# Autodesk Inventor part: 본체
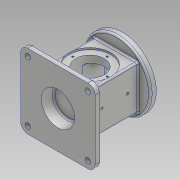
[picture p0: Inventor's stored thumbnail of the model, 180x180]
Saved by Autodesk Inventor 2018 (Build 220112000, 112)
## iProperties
Created: 2021-05
Part Number: 본체
Material: 알루미늄 6061
Document SubType Name: Modeling
Designer: home
Density: 2.7 g/cm^3
Appearance: 알루미늄 - 평지
Mass: 1251.58 g
Surface Area: 895.233 cm^2
Volume: 463.547 cm^3
Author: home
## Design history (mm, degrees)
sketch "스케치2"
  geometry: L1 (37, -37)-(-37, -37); L2 (-37, -37)-(-37, 37); L3 (-37, 37)-(37, 37); L4 (37, 37)-(37, -37); 1 further point
  constraints: 8 end point, 2 parallel, 1 horizontal, 1 perpendicular
  dimensions: "d4" = 74 distance between parallel lines of L2 L4; "d5" = 74 distance between parallel lines of L3 L1; "d6" = 37 distance from line of point (0, 0) L1; "d7" = 37 distance from line of point (0, 0) L4
extrude "돌출1" new body sketch "스케치2" distance "d8" = 88; taper "d9" = 0 deg
sketch "스케치3"
  geometry: L1 (74, 0)-(0, 0) reference; C1 r 24 at (37, 44); 2 further points
  constraints: 1 centre point, 1 midpoint, 1 vertical alignment
  dimensions: "d10" = 48 diameter of C1; "d11" = 44 distance from line of L1 C1.centre
extrude "돌출2" cut sketch "스케치3" distance "d12" = 88; taper "d13" = 0 deg
sketch "스케치4"
  geometry: C1 r 57.5 at (0, 0); 1 further point
  constraints: 1 centre point, 1 coincident
  dimensions: "d14" = 115 diameter of C1
extrude "돌출3" join sketch "스케치4" distance "d15" = 10; taper "d16" = 0 deg
sketch "스케치7"
  geometry: L1 (74, 0)-(0, 0) reference; L2 (74, 0)-(74, 88) reference; L3 (0, 88)-(74, 88) reference; L4 (0, 0)-(0, 88) reference; C1 r 24 at (37, 44) reference; C2 r 35 at (37, 44); 1 further point
  constraints: 1 centre point, 1 coincident
  dimensions: "d23" = 70 diameter of C2
extrude "돌출6" cut sketch "스케치7" distance "d24" = 3; taper "d25" = 0 deg
sketch "스케치8"
  geometry: L1 (37, -44)-(-37, -44) reference; C1 r 24 at (0, 0) reference; C2 r 35 at (0, 0) reference; 3 further points
  constraints: 1 midpoint, 1 vertical alignment
  dimensions: "d27" = 29 distance of point (0, 29) C1.centre
hole "구멍1" sketch "스케치8" at (0, 29) diameter "d28" = 3.242; stored, may be unused: countersink angle "d32" = 90 deg, drill point angle "d34" = 118 deg; dims "d29" = 8, "d30" = 4, "d31" = 2, "d33" = 10
sketch "스케치9"
  geometry: L1 (74, 0)-(0, 0) reference; 5 further points
  constraints: 2 midpoint, 2 vertical alignment
  dimensions: "d38" = 43 distance of point (37, 70) point (37, 27); "d39" = 27 distance of point (37, 0) point (37, 27)
hole "구멍2" sketch "스케치9" at (37, 70), (37, 27) diameter "d40" = 4.134; stored, may be unused: countersink angle "d44" = 90 deg, drill point angle "d46" = 118 deg; dims "d41" = 30, "d42" = 4, "d43" = 2, "d45" = 30
sketch "스케치10"
  geometry: L1 (-26, -26)-(26, -26); L2 (26, -26)-(26, 26); L3 (26, 26)-(-26, 26); L4 (-26, 26)-(-26, -26); 1 further point
  constraints: 8 end point, 2 parallel, 1 horizontal, 1 perpendicular
  dimensions: "d47" = 26 distance from line of point (0, 0) L1; "d48" = 52 distance between parallel lines of L3 L1; "d49" = 26 distance from line of point (0, 0) L4; "d50" = 52 distance between parallel lines of L2 L4
extrude "돌출7" cut sketch "스케치10" distance "d51" = 8; taper "d52" = 0 deg
sketch "스케치11"
  geometry: L1 (-22, -22)-(22, -22); L2 (22, -22)-(22, 22); L3 (22, 22)-(-22, 22); L4 (-22, 22)-(-22, -22); 1 further point
  constraints: 8 end point, 2 parallel, 1 horizontal, 1 perpendicular
  dimensions: "d53" = 22 distance from line of point (0, 0) L1; "d54" = 44 distance between parallel lines of L3 L1; "d55" = 22 distance from line of L4 point (0, 0); "d56" = 44 distance between parallel lines of L2 L4
extrude "돌출8" cut sketch "스케치11" distance "d57" = 74; taper "d58" = 0 deg
sketch "스케치13"
  geometry: L1 (33, -30)-(-33, -30); L2 (-33, -30)-(-33, 30); L3 (-33, 30)-(33, 30); L4 (33, 30)-(33, -30); 5 further points
  constraints: 8 end point, 4 coincident, 2 parallel, 1 horizontal, 1 perpendicular
  dimensions: "d59" = 66 distance of L1.start L1.end; "d60" = 60 distance of L1.end L2.end; "d61" = 30 distance from line of L3 point (0, 0); "d62" = 33 distance from line of point (0, 0) L4
hole "구멍3" sketch "스케치13" at (33, -30), (-33, -30), (-33, 30), (33, 30) diameter "d63" = 3.242; stored, may be unused: countersink angle "d67" = 90 deg, drill point angle "d69" = 118 deg; dims "d64" = 8, "d65" = 4, "d66" = 2, "d68" = 10
fillet "모깎기1" dims "d70" = 6
fillet "모깎기2" dims "d71" = 3
fillet "모깎기3" dims "d72" = 3
chamfer "모따기1" distance "d73" = 1; stored, may be unused: second distance "d74" = 2, angle "d75" = 45 deg
sketch "스케치14"
  geometry: L1 (-62.5, 62.5)-(62.5, 62.5); L2 (62.5, 62.5)-(62.5, -62.5); L3 (62.5, -62.5)-(-62.5, -62.5); L4 (-62.5, -62.5)-(-62.5, 62.5); 1 further point
  constraints: 8 end point, 2 parallel, 1 horizontal, 1 perpendicular
  dimensions: "d76" = 62.5 distance from line of L4 point (0, 0); "d77" = 125 distance between parallel lines of L2 L4; "d78" = 125 distance between parallel lines of L3 L1; "d79" = 62.5 distance from line of L3 point (0, 0)
extrude "돌출9" join sketch "스케치14" distance "d80" = 10; taper "d81" = 0 deg
fillet "모깎기4" dims "d82" = 12
sketch "스케치15"
  geometry: L1 (-62.5, -50.5)-(-62.5, 50.5) reference; L2 (-50.5, 62.5)-(50.5, 62.5) reference; L3 (62.5, 50.5)-(62.5, -50.5) reference; L4 (50.5, -62.5)-(-50.5, -62.5) reference; C1 r 4.5 at (-50.5, 50.5); C2 r 4.5 at (-50.5, -50.5); C3 r 4.5 at (50.5, -50.5); C4 r 4.5 at (50.5, 50.5); A1 r 12 centre (-50.5, -50.5) between (-62.5, -50.5) and (-50.5, -62.5) reference; A2 r 12 centre (-50.5, 50.5) between (-50.5, 62.5) and (-62.5, 50.5) reference; A3 r 12 centre (50.5, 50.5) between (62.5, 50.5) and (50.5, 62.5) reference; A4 r 12 centre (50.5, -50.5) between (50.5, -62.5) and (62.5, -50.5) reference; 1 further point
  constraints: 4 centre point, 4 coincident
  dimensions: "d83" = 9 diameter of C1; "d84" = 9 diameter of C2; "d85" = 9 diameter of C3; "d86" = 9 diameter of C4
extrude "돌출10" cut sketch "스케치15" distance "d87" = 10; taper "d88" = 0 deg
fillet "모깎기5" dims "d89" = 3
sketch "스케치16"
  geometry: 2 further points
  constraints: 1 vertical alignment, 1 other
  dimensions: "d90" = 55 distance of point (0, -55) point (0, 0)
feature "엠보싱1" sketch "스케치16" dims "d4" = 74, "d5" = 74, "d6" = 37, "d7" = 37, "d91" = 0.5, "d92" = 0
fillet "모깎기6" dims "d93" = 3
fillet "모깎기7" dims "d94" = 3
sketch "스케치17"
  geometry: C1 r 28 at (0, 0); 1 further point
  constraints: 1 centre point, 1 coincident
  dimensions: "d95" = 56 diameter of C1
extrude "돌출11" cut sketch "스케치17" distance "d96" = 18; taper "d97" = -10 deg
fillet "모깎기8" dims "d98" = 3
fillet "모깎기9" dims "d99" = 3
node "솔리드1"
pattern_circular "원형 패턴1" dims angle "d36" = 360 deg
mirror "미러1"
node "투영된 루프1"
node "투영된 루프2"
node "투영된 루프3"
